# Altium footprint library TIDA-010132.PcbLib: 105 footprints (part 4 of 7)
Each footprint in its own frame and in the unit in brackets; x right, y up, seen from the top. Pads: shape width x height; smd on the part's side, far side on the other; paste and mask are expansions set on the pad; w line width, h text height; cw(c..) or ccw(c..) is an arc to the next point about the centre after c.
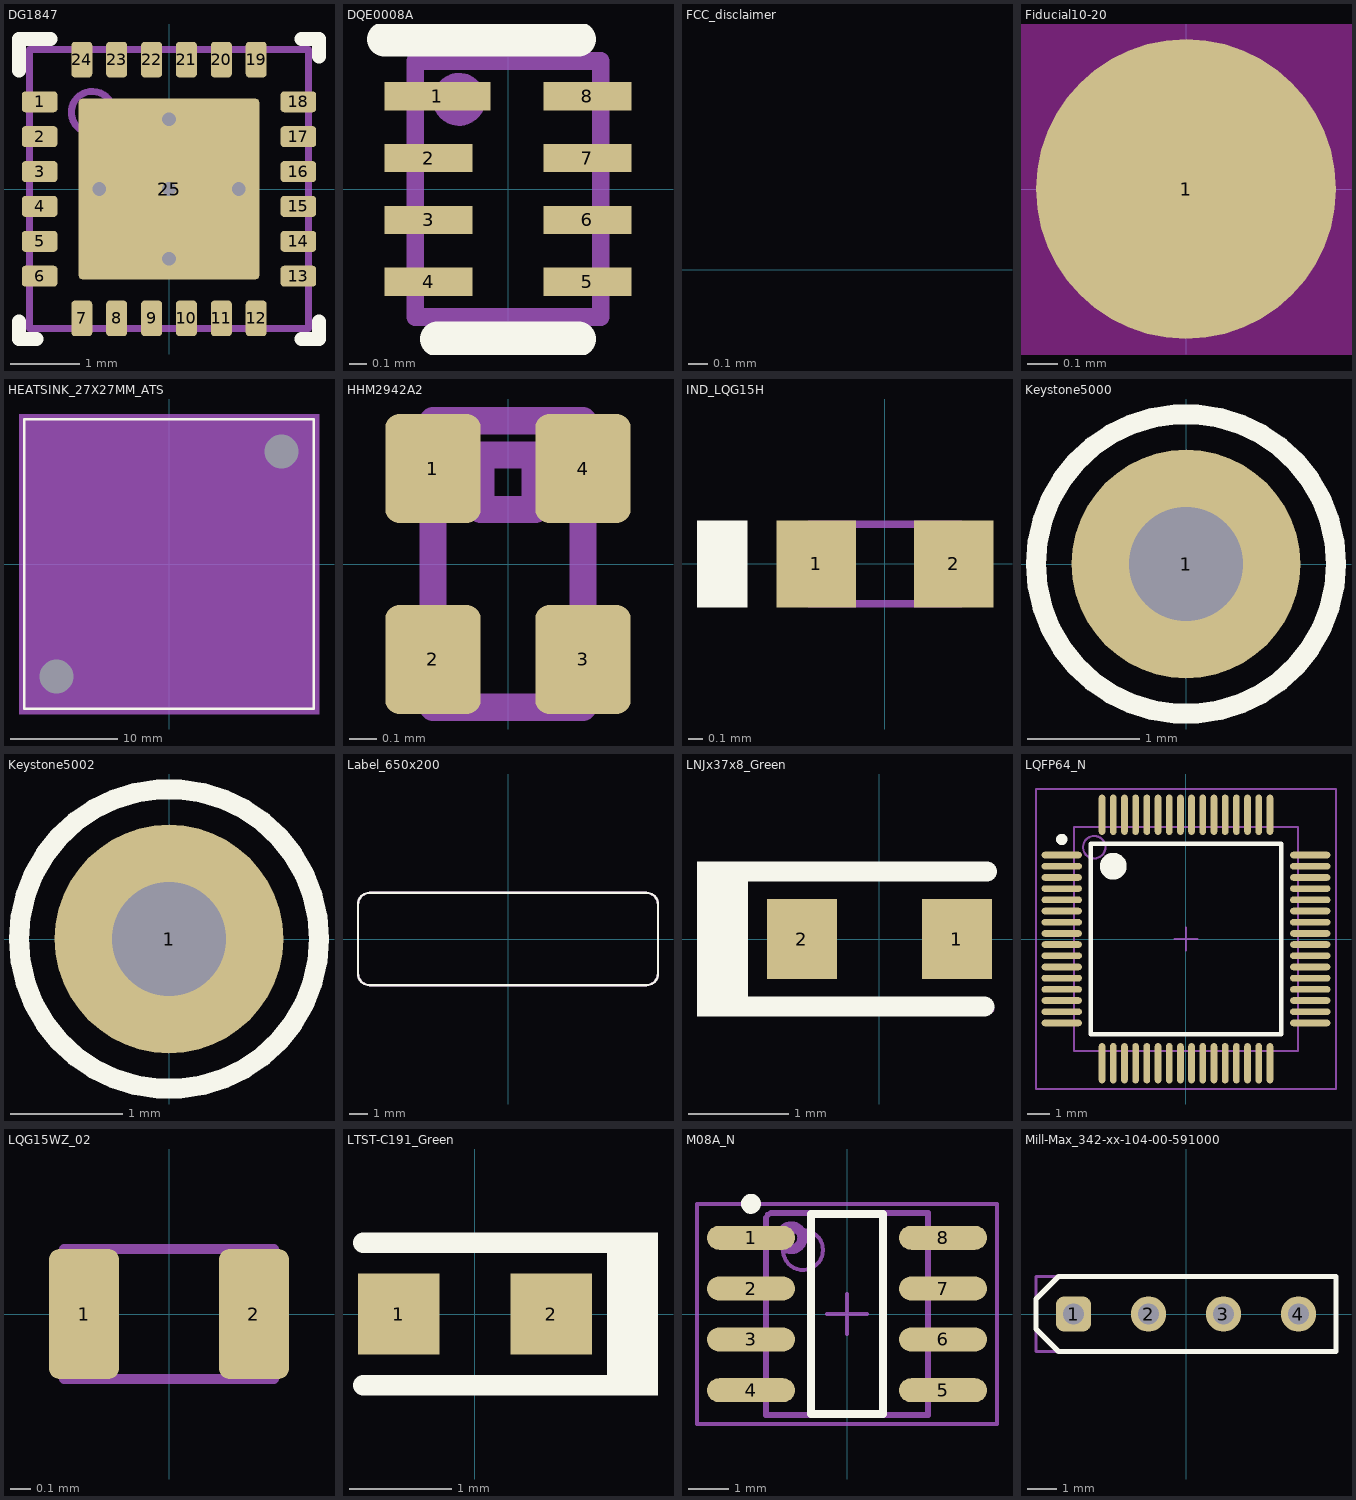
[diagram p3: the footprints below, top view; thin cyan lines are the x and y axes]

## DG1847 [mm] "QFN, 24-Leads, Body 4x4mm, Pitch 0.5mm"
height 1
pads (29):
  rrect33% 0.51x0.3 smd: 1(-1.855,1.25) 2(-1.855,0.75) 3(-1.855,0.25) 4(-1.855,-0.25) 5(-1.855,-0.75) 6(-1.855,-1.25) 13(1.855,-1.25) 14(1.855,-0.75) 15(1.855,-0.25) 16(1.855,0.25) 17(1.855,0.75) 18(1.855,1.25)
  rrect33% 0.3x0.51 smd: 7(-1.25,-1.855) 8(-0.75,-1.855) 9(-0.25,-1.855) 10(0.25,-1.855) 11(0.75,-1.855) 12(1.25,-1.855) 19(1.25,1.855) 20(0.75,1.855) 21(0.25,1.855) 22(-0.25,1.855) 23(-0.75,1.855) 24(-1.25,1.855)
  rrect4% 2.59x2.59 smd paste-2: 25(0,0)
  rrect50% 1.106x1.106 on Top Paste: ""(-0.653,-0.653) ""(-0.653,0.653) ""(0.653,-0.653) ""(0.653,0.653)
via 0,1 diameter 0.5 hole 0.2
via 0,0 diameter 0.5 hole 0.2
via -1,0 diameter 0.5 hole 0.2
via 0,-1 diameter 0.5 hole 0.2
via 1,0 diameter 0.5 hole 0.2
Top Overlay:
  lines w0.2: -2.15,-1.9 -2.15,-2.15 -1.9,-2.15 ; -2.15,1.7 -2.15,2.15 -1.7,2.15 ; 1.9,-2.15 2.15,-2.15 2.15,-1.9 ; 1.9,2.15 2.15,2.15 2.15,1.9
Mechanical 5:
  circle w0.1: c-1.1,1.1 r0.3
  lines w0.1: -2,-2 2,-2 2,2 -2,2 -2,-2
  text ".Designator" at -2,-0.7 h0.46
3D body "DG1847.stp": height 1, standoff 0, extent -2.001,-2.001 2.001,2.001

## DQE0008A [mm] "SON, 8-Leads, Body 1.4x1mm, Pitch 0.35mm, TI Recommended"
height 0.4
pads (8):
  rect 0.6x0.16 smd: 1(-0.4,0.525)
  rect 0.5x0.16 smd: 2(-0.45,0.175) 3(-0.45,-0.175) 4(-0.45,-0.525) 5(0.45,-0.525) 6(0.45,-0.175) 7(0.45,0.175) 8(0.45,0.525)
Top Overlay:
  lines w0.2: -0.7,0.85 0.4,0.85 ; -0.4,-0.85 0.4,-0.85
Mechanical 5:
  circle w0.1: c-0.277,0.508 r0.1
  lines w0.1: -0.525,-0.725 -0.525,0.725 0.525,0.725 0.525,-0.725 -0.525,-0.725
  text ".Designator" at 0.075,0.45 h0.46
3D body: height 0.4, standoff 0, extent -0.525,-0.725 0.525,0.725
3D body: height 0.41, standoff 0.2, extent -0.376,0.409 -0.178,0.607

## FCC_disclaimer [mil]
Top Overlay:
  text "For evaluation only; not FCC approved for resale." at -627.08,-13.9 h60

## Fiducial10-20 [mm]
height 7.6
pads (1):
  round 1 smd mask+0.5: 1(0,0)
Top Layer keep-out:
  circle w1.178: c0,0 r0.5

## HEATSINK_27X27MM_ATS [mil] "HEATSINK_27X27MM_ATS"
pads (2):
  round 0 hole 125 unplated: MTG1(-413.39,-413.39) MTG2(413.39,413.39)
Top Overlay:
  lines w10: -531.5,-531.5 -531.5,531.5 531.5,531.5 531.5,-531.5 -531.5,-531.5
Mechanical 16:
  circle w1: c413.38,413.38 r125.01
  circle w1: c413.38,413.38 r62.51
  circle w1: c-413.38,-413.38 r62.49
  circle w1: c-413.38,-413.38 r124.99
  region: -551.18,-551.18 551.18,-551.18 551.18,551.18 -551.18,551.18
  lines w1: -531.5,-531.5 531.5,-531.5 531.5,531.5 -531.5,531.5 -531.5,-531.5
Mechanical 22:
  text "MTG1" at -543.39,-413.39 h25
  text "MTG2" at 283.39,413.39 h25
Mechanical 23:
  text ".Designator" at -160,700 h50
3D body: height 150, standoff 0, extent -551.18,-551.18 551.18,551.18

## HHM2942A2 [mm] "SMD, 4-Leads, Body 1x0.5mm"
height 0.4
pads (4):
  rrect29% 0.35x0.4 smd: 1(-0.275,0.35) 2(-0.275,-0.35) 3(0.275,-0.35) 4(0.275,0.35)
Mechanical 5:
  lines w0.1: -0.275,-0.525 0.275,-0.525 0.275,0.525 -0.275,0.525 -0.275,-0.525 ; -0.1,0.2 0.1,0.2 0.1,0.4 -0.1,0.4 -0.1,0.2
  text ".Designator" at -0.075,0.15 h0.46
3D body: height 0.4, standoff 0, extent -0.275,-0.525 0.275,0.525
3D body: height 0.4, standoff 0.4, extent -0.1,0.2 0.1,0.4

## IND_LQG15H [mm] "MuRata"
height 0.55
pads (2):
  rect 0.55x0.6 smd: 1(-0.475,0) 2(0.475,0)
Top Overlay:
  rectangle: -1.3,-0.3 -0.95,0.3
Mechanical 5:
  rectangle: -0.7,-0.275 -0.525,0.275
  lines w0.05: -0.525,-0.275 0.525,-0.275 0.525,0.275 -0.525,0.275 -0.525,-0.275
  text ".Designator" at -0.45,-0.125 h0.46
3D body: height 0.55, standoff 0, extent -0.524,-0.274 -0.276,0.275
3D body: height 0.54, standoff 0, extent -0.274,-0.274 0.274,0.275
3D body: height 0.55, standoff 0, extent 0.276,-0.274 0.524,0.275
3D body: height 0.55, standoff 0.54, extent -0.274,-0.274 -0.001,0.275

## Keystone5000 [mil] "For Keystone 500x miniature loop terminals"
height 181.1
pads (1):
  round 80 hole 40: 1(0,0)
Top Overlay:
  circle w7: c0,0 r52.5
Mechanical 5:
  circle w3.94: c0,0 r52.5
  text ".Designator" at -92.97,-15 h18
3D body "Keystone_5000.stp": height 181.97, standoff -118.11, extent -49,-49 49.04,49.23

## Keystone5002 [mil] "For Keystone 500x miniature loop terminals"
height 181.1
pads (1):
  round 80 hole 40: 1(0,0)
Top Overlay:
  circle w7: c0,0 r52.5
Mechanical 5:
  circle w3.94: c0,0 r52.5
  text ".Designator" at 119.79,38.91 h18
3D body "Keystone_5002.stp": height 181.97, standoff -118.11, extent -49,-49 49.04,49.23

## Label_650x200 [mil] "Thermal Transfer Label"
height 1
pads (1):
  round 1 on Mech13: 0(0,0)
Top Overlay:
  lines w5: -325,-75 ccw(c-300,-75) -300,-100 300,-100 ccw(c300,-75) 325,-75 325,75 ccw(c300,75) 300,100 -300,100 ccw(c-300,75) -325,75 -325,-75
Mechanical 5:
  lines w5: -325,-75 ccw(c-300,-75) -300,-100 300,-100 ccw(c300,-75) 325,-75 325,75 ccw(c300,75) 300,100 -300,100 ccw(c-300,75) -325,75 -325,-75
  text ".Designator" at -60,-20 h18
3D body: height 1, standoff 0, extent -325.02,-100.02 325.02,100.02

## LNJx37x8_Green [mm] "SMD, 2-Leads, Body 1.6x0.8mm"
height 0.25
pads (2):
  rect 0.7x0.8 smd: 1(0.775,0) 2(-0.775,0)
Top Overlay:
  region: -1.317,0.776 -1.825,0.776 -1.825,-0.774 -1.317,-0.774
  lines w0.2: -1.45,-0.675 1.05,-0.675 ; -1.425,0.675 1.075,0.675
Mechanical 5:
  region: -1.4,0.75 -1.825,0.75 -1.825,-0.75 -1.4,-0.75
  lines w0.1: -1.626,-0.7 1.1,-0.7 ; -1.626,0.7 1.1,0.7
  text ".Designator" at -1.3,-0.2 h0.46
3D body: height 0.1, standoff 0.01, extent 0.551,-0.449 0.849,0.449
3D body: height 0.1, standoff 0.01, extent -0.849,-0.449 -0.551,0.449
3D body: height 0.1, standoff 0.01, extent -0.549,-0.449 0.549,0.449
3D body: height 0.25, standoff 0.1, extent -0.549,-0.449 0.549,0.449
3D body: height 0.11, standoff 0.1, extent 0.551,-0.449 0.849,0.449
3D body: height 0.11, standoff 0.1, extent -0.849,-0.449 -0.551,0.449
3D body: height 0.01, standoff 0, extent -0.301,-0.401 0.101,0.401

## LQFP64_N [mm] "Thin QFP, 64-Leads, Body 10x10mm, Pitch 0.5mm, IPC Medium Density"
height 1.6
pads (64):
  oval 1.8x0.3 smd: 1(-5.55,3.75) 2(-5.55,3.25) 3(-5.55,2.75) 4(-5.55,2.25) 5(-5.55,1.75) 6(-5.55,1.25) 7(-5.55,0.75) 8(-5.55,0.25) 9(-5.55,-0.25) 10(-5.55,-0.75) 11(-5.55,-1.25) 12(-5.55,-1.75) 13(-5.55,-2.25) 14(-5.55,-2.75) 15(-5.55,-3.25) 16(-5.55,-3.75) 33(5.55,-3.75) 34(5.55,-3.25) 35(5.55,-2.75) 36(5.55,-2.25) 37(5.55,-1.75) 38(5.55,-1.25) 39(5.55,-0.75) 40(5.55,-0.25) 41(5.55,0.25) 42(5.55,0.75) 43(5.55,1.25) 44(5.55,1.75) 45(5.55,2.25) 46(5.55,2.75) 47(5.55,3.25) 48(5.55,3.75)
  oval 0.3x1.8 smd: 17(-3.75,-5.55) 18(-3.25,-5.55) 19(-2.75,-5.55) 20(-2.25,-5.55) 21(-1.75,-5.55) 22(-1.25,-5.55) 23(-0.75,-5.55) 24(-0.25,-5.55) 25(0.25,-5.55) 26(0.75,-5.55) 27(1.25,-5.55) 28(1.75,-5.55) 29(2.25,-5.55) 30(2.75,-5.55) 31(3.25,-5.55) 32(3.75,-5.55) 49(3.75,5.55) 50(3.25,5.55) 51(2.75,5.55) 52(2.25,5.55) 53(1.75,5.55) 54(1.25,5.55) 55(0.75,5.55) 56(0.25,5.55) 57(-0.25,5.55) 58(-0.75,5.55) 59(-1.25,5.55) 60(-1.75,5.55) 61(-2.25,5.55) 62(-2.75,5.55) 63(-3.25,5.55) 64(-3.75,5.55)
Top Overlay:
  circle w0.25: c-5.55,4.45 r0.125
  circle w0.6: c-3.25,3.25 r0.3
  lines w0.2: -4.25,-4.25 -4.25,4.25 4.25,4.25 4.25,-4.25 -4.25,-4.25
Mechanical 5:
  circle w0.1: c-4.1,4.1 r0.5
  lines w0.1: -5,-5 -5,5 5,5 5,-5 -5,-5
  text ".Designator" at -1.524,-0.508 h0.46
Mechanical 15:
  lines w0.1: -0.5,0 0.5,0 ; 0,-0.5 0,0.5 ; -6.7,-6.7 -6.7,6.7 6.7,6.7 6.7,-6.7 -6.7,-6.7
3D body: height 1.6, standoff 0, extent -5,-5 5,5

## LQG15WZ_02 [mm] "MuRata recommended land pattern"
height 0.6
pads (2):
  rrect29% 0.35x0.65 smd: 1(-0.425,0) 2(0.425,0)
Mechanical 5:
  lines w0.05: -0.525,-0.325 -0.525,0.325 0.525,0.325 0.525,-0.325 -0.525,-0.325
  text ".Designator" at -0.4,-0.068 h0.46
3D body: height 0.6, standoff 0, extent 0.326,-0.324 0.524,0.324
3D body: height 0.6, standoff 0, extent -0.324,-0.324 0.324,0.324
3D body: height 0.6, standoff 0, extent -0.524,-0.324 -0.326,0.324

## LTST-C191_Green [mm] "Lite-On"
height 0.65
pads (2):
  rect 0.8x0.8 smd: 1(-0.75,0) 2(0.75,0)
Top Overlay:
  region: 1.8,0.8 1.3,0.8 1.3,-0.8 1.8,-0.8
  lines w0.2: -1.1,-0.7 1.4,-0.7 ; -1.1,0.7 1.4,0.7
Mechanical 5:
  region: 1.8,0.75 1.3,0.75 1.3,-0.75 1.8,-0.75
  lines w0.1: -1.1,-0.7 1.4,-0.7 ; -1.1,0.7 1.4,0.7
  text ".Designator" at -0.378,-0.316 h0.46
3D body: height 0.65, standoff 0.2, extent -0.624,-0.449 0.624,0.449
3D body: height 0.2, standoff 0, extent -0.849,-0.449 0.849,0.449

## M08A_N [mm] "SOIC, 8-Leads, Body 4.9x3.9mm, Pitch 1.27mm, IPC Medium Density"
height 1.75
pads (8):
  oval 2.2x0.6 smd: 1(-2.4,1.905) 2(-2.4,0.635) 3(-2.4,-0.635) 4(-2.4,-1.905) 5(2.4,-1.905) 6(2.4,-0.635) 7(2.4,0.635) 8(2.4,1.905)
Top Overlay:
  circle w0.25: c-2.4,2.755 r0.125
  lines w0.2: -0.9,-2.5 -0.9,2.5 0.9,2.5 0.9,-2.5 -0.9,-2.5
Mechanical 5:
  circle w0.254: c-1.397,1.905 r0.284
  lines w0.127: -2.032,-2.54 2.032,-2.54 2.032,2.54 -1.905,2.54 -2.032,2.413 -2.032,-2.54
  text ".Designator" at 2.319,0.507 h0.46
Mechanical 13:
  circle w0.1: c-1.1,1.6 r0.5
  lines w0.1: -2,-2.5 -2,2.5 2,2.5 2,-2.5 -2,-2.5
Mechanical 15:
  lines w0.1: -0.5,0 0.5,0 ; 0,-0.5 0,0.5 ; -3.75,-2.75 -3.75,2.75 3.75,2.75 3.75,-2.75 -3.75,-2.75
3D body: height 1.75, standoff 0, extent -2,-2.5 2,2.5

## Mill-Max_342-xx-104-00-591000 [mm] "Mill-Max"
height 8.509
pads (4):
  rrect50% 1.2x1.2 hole 0.7: 1(-3.81,0)
  round 1.2 hole 0.7: 2(-1.27,0) 3(1.27,0) 4(3.81,0)
Top Overlay:
  lines w0.178: -5.08,-0.508 -4.318,-1.27 5.08,-1.27 5.08,1.27 -4.318,1.27 -5.08,0.508 -5.08,-0.508
Mechanical 5:
  lines w0.102: -5.08,-1.27 -5.08,1.27 5.08,1.27 5.08,-1.27 -5.08,-1.27
  text ".Designator" at -2.032,-0.508 h0.46
3D body: height 3.28, standoff 0.48, extent -5.079,-1.269 5.079,1.269
3D body: height 0, standoff -3.17, extent 3.583,-0.228 4.039,0.228
3D body: height 1.27, standoff 0, extent 3.256,-0.558 4.369,0.558
3D body: height 3.56, standoff 1.27, extent 2.903,-0.912 4.725,0.913
3D body: height 5.33, standoff 3.56, extent 3.18,-0.634 4.445,0.634
3D body: height 8.51, standoff 5.33, extent 3.583,-0.228 4.039,0.228
3D body: height 0, standoff -3.17, extent 1.043,-0.228 1.499,0.228
3D body: height 1.27, standoff 0, extent 0.716,-0.558 1.829,0.558
3D body: height 3.56, standoff 1.27, extent 0.363,-0.912 2.185,0.913
3D body: height 5.33, standoff 3.56, extent 0.64,-0.634 1.905,0.634
3D body: height 8.51, standoff 5.33, extent 1.043,-0.228 1.499,0.228
3D body: height 0, standoff -3.17, extent -1.497,-0.228 -1.041,0.228
3D body: height 1.27, standoff 0, extent -1.824,-0.558 -0.711,0.558
3D body: height 3.56, standoff 1.27, extent -2.177,-0.912 -0.355,0.913
3D body: height 5.33, standoff 3.56, extent -1.9,-0.634 -0.635,0.634
3D body: height 8.51, standoff 5.33, extent -1.497,-0.228 -1.041,0.228
3D body: height 0, standoff -3.17, extent -4.037,-0.228 -3.581,0.228
3D body: height 1.27, standoff 0, extent -4.364,-0.558 -3.251,0.558
3D body: height 3.56, standoff 1.27, extent -4.717,-0.912 -2.895,0.913
3D body: height 5.33, standoff 3.56, extent -4.44,-0.634 -3.175,0.634
3D body: height 8.51, standoff 5.33, extent -4.037,-0.228 -3.581,0.228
